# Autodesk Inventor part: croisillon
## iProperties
Author: robert
Shininess: 20.0
PropertySet Name: _Private Model Information
Compacted: True
Length Units: 11269
Angle Units: 11283
Time Units: 11279
Mass Units: 11290
Length Display Precision: 3
Angle Display Precision: 2
Created: 2001-07
Part Number: croisillon
Material: Par défaut
Document SubType Name: Modélisation
Designer: robert
Control State: 0
Master: False
Checked Out: False
PropertySet Name: Design Tracking Control
Density: 0.0
Volumn: 0.0
Area: 0.0
PropertySet Name: Model Information
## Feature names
1. Révolution1 [Revolution]
2. Chanfrein1 [Chamfer]
3. Extrusion1
4. Extrusion2
5. Congé1 [Fillet]
